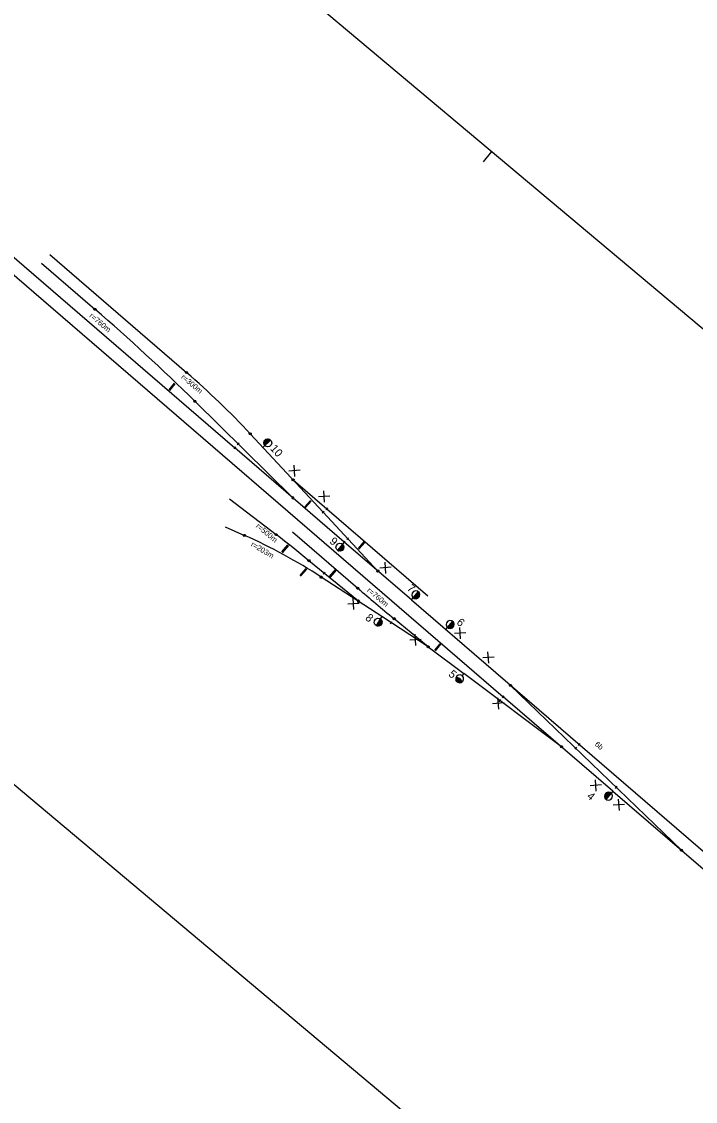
# Model space of a CAD drawing. Extents: x -473608 to -471381, y -1324122 to -1322275.
# Drawn here: x -472467.4 to -472214.7, y -1323575.9 to -1323171.1 of the extents above; entities that cross this region are included whole.
import ezdxf

# ---------------------------------------------------------------- set-up
doc = ezdxf.new("R2010")
doc.units = 0
for name, color, linetype in [('Level 1', 7, 'Continuous'), ('Level 10', 7, 'Continuous'), ('Level 11', 7, 'Continuous'), ('Level 61', 7, 'Continuous')]:
    doc.layers.add(name, color=color, linetype=linetype)

msp = doc.modelspace()

# ---------------------------------------------------------------- linework, layer by layer
at = {"layer": 'Level 1'}
for p, q in [((-472667.69, -1323096.2), (-472286.75, -1323424.15)), ((-472664.42, -1323092.41), (-472387.48, -1323330.83)), ((-472459.93, -1323261.65), (-472439.88, -1323278.91)), ((-472456.85, -1323258.45), (-472405.55, -1323302.62)), ((-472439.88, -1323278.91), (-472439.88, -1323278.91)), ((-472405.55, -1323302.62), (-472405.55, -1323302.62)), ((-472365.7, -1323349.58), (-472402.43, -1323313.4)), ((-472402.43, -1323313.4), (-472402.43, -1323313.4)), ((-472381.63, -1323325.64), (-472354.29, -1323355.02)), ((-472381.63, -1323325.64), (-472381.63, -1323325.64)), ((-472387.16, -1323330.45), (-472387.81, -1323331.21)), ((-472346.4, -1323366.2), (-472387.48, -1323330.83)), ((-472387.48, -1323330.83), (-472387.48, -1323330.83)), ((-472385.83, -1323329.06), (-472386.53, -1323329.77)), ((-472386.18, -1323329.41), (-472386.18, -1323329.41)), ((-472365.61, -1323342.86), (-472365.61, -1323342.86)), ((-472365.61, -1323342.86), (-472315.12, -1323386.32)), ((-472389.38, -1323349.97), (-472371.92, -1323363.41)), ((-472365.7, -1323349.58), (-472365.7, -1323349.58)), ((-472353.92, -1323354.68), (-472354.66, -1323355.36)), ((-472333.8, -1323377.04), (-472354.29, -1323355.02)), ((-472354.29, -1323355.02), (-472354.29, -1323355.02)), ((-472352.69, -1323353.32), (-472353.34, -1323354.08)), ((-472353.02, -1323353.7), (-472353.02, -1323353.7)), ((-472391.07, -1323360.46), (-472383.79, -1323363.68)), ((-472371.92, -1323363.41), (-472371.92, -1323363.41)), ((-472365.84, -1323362.37), (-472341.31, -1323383.48)), ((-472383.79, -1323363.68), (-472383.79, -1323363.68)), ((-472346.74, -1323366.57), (-472346.05, -1323365.84)), ((-472321.21, -1323387.89), (-472346.4, -1323366.2)), ((-472346.4, -1323366.2), (-472346.4, -1323366.2)), ((-472345.49, -1323365.22), (-472344.76, -1323364.54)), ((-472345.49, -1323365.22), (-472344.76, -1323364.54)), ((-472345.12, -1323364.88), (-472345.12, -1323364.88)), ((-472345.12, -1323364.88), (-472345.12, -1323364.88)), ((-472341.1, -1323388.4), (-472359.63, -1323373.18)), ((-472359.63, -1323373.18), (-472359.63, -1323373.18)), ((-472359.63, -1323373.18), (-472359.63, -1323373.18)), ((-472354.75, -1323378.92), (-472355.3, -1323379.76)), ((-472355.03, -1323379.32), (-472355.03, -1323379.32)), ((-472332.28, -1323394.14), (-472355.02, -1323379.34)), ((-472355.02, -1323379.34), (-472355.02, -1323379.34)), ((-472353.62, -1323377.47), (-472354.26, -1323378.24)), ((-472353.94, -1323377.85), (-472353.94, -1323377.85)), ((-472333.8, -1323377.04), (-472333.8, -1323377.04)), ((-472341.31, -1323383.48), (-472341.31, -1323383.48)), ((-472341.1, -1323388.4), (-472341.1, -1323388.4)), ((-472321.21, -1323387.89), (-472146.88, -1323537.97)), ((-472314.89, -1323405.45), (-472332.28, -1323394.14)), ((-472328.05, -1323395.29), (-472327.41, -1323394.52)), ((-472327.73, -1323394.9), (-472327.73, -1323394.9)), ((-472314.89, -1323405.45), (-472327.73, -1323394.9)), ((-472327.73, -1323394.9), (-472327.73, -1323394.9)), ((-472329.09, -1323396.81), (-472328.54, -1323395.97)), ((-472328.82, -1323396.39), (-472328.82, -1323396.39)), ((-472314.89, -1323405.45), (-472314.89, -1323405.45)), ((-472314.89, -1323405.45), (-472301.6, -1323415.42)), ((-472264.97, -1323442.91), (-472301.6, -1323415.42)), ((-472284.03, -1323419.9), (-472284.03, -1323419.9)), ((-472284.03, -1323419.9), (-472219.91, -1323481.7)), ((-472287.08, -1323424.53), (-472286.43, -1323423.78)), ((-472245.67, -1323459.53), (-472286.75, -1323424.15)), ((-472286.75, -1323424.15), (-472286.75, -1323424.15)), ((-472288.26, -1323426.05), (-472287.66, -1323425.26)), ((-472287.96, -1323425.66), (-472287.96, -1323425.66)), ((-472264.97, -1323442.91), (-472264.97, -1323442.91)), ((-472259.85, -1323443.86), (-472259.21, -1323443.1)), ((-472259.53, -1323443.48), (-472259.53, -1323443.48)), ((-472258.56, -1323442.47), (-472257.92, -1323441.7)), ((-472258.24, -1323442.08), (-472258.24, -1323442.08)), ((-472245.67, -1323459.53), (-472195.63, -1323502.6)), ((-472244.7, -1323458.51), (-472244.06, -1323457.74)), ((-472244.38, -1323458.12), (-472244.38, -1323458.12)), ((-472219.91, -1323481.7), (-472219.91, -1323481.7))]:
    msp.add_line(p, q, dxfattribs=at)
for points in [[(-472439.62, -1323278.61), (-472439.49, -1323278.99), (-472439.75, -1323279.29), (-472440.14, -1323279.22), (-472440.27, -1323278.84), (-472440.02, -1323278.53), (-472439.62, -1323278.61)], [(-472405.29, -1323302.32), (-472405.15, -1323302.7), (-472405.41, -1323303), (-472405.81, -1323302.93), (-472405.94, -1323302.55), (-472405.68, -1323302.25), (-472405.29, -1323302.32)], [(-472402.72, -1323313.69), (-472402.82, -1323313.3), (-472402.54, -1323313.02), (-472402.16, -1323313.12), (-472402.05, -1323313.5), (-472402.33, -1323313.79), (-472402.72, -1323313.69)], [(-472381.92, -1323325.91), (-472382.01, -1323325.52), (-472381.72, -1323325.25), (-472381.34, -1323325.37), (-472381.25, -1323325.76), (-472381.54, -1323326.03), (-472381.92, -1323325.91)], [(-472365.34, -1323343.15), (-472365.73, -1323343.24), (-472366, -1323342.95), (-472365.88, -1323342.56), (-472365.49, -1323342.48), (-472365.22, -1323342.77), (-472365.34, -1323343.15)], [(-472365.98, -1323349.87), (-472365.59, -1323349.97), (-472365.32, -1323349.69), (-472365.42, -1323349.3), (-472365.81, -1323349.2), (-472366.09, -1323349.48), (-472365.98, -1323349.87)], [(-472383.62, -1323363.31), (-472383.39, -1323363.64), (-472383.55, -1323364), (-472383.95, -1323364.05), (-472384.18, -1323363.72), (-472384.02, -1323363.36), (-472383.62, -1323363.31)], [(-472371.68, -1323363.09), (-472371.53, -1323363.46), (-472371.77, -1323363.78), (-472372.17, -1323363.73), (-472372.32, -1323363.35), (-472372.07, -1323363.04), (-472371.68, -1323363.09)], [(-472359.88, -1323373.49), (-472360.02, -1323373.12), (-472359.77, -1323372.81), (-472359.38, -1323372.87), (-472359.24, -1323373.25), (-472359.49, -1323373.56), (-472359.88, -1323373.49)], [(-472359.38, -1323372.87), (-472359.24, -1323373.25), (-472359.49, -1323373.55), (-472359.88, -1323373.49), (-472360.02, -1323373.11), (-472359.77, -1323372.81), (-472359.38, -1323372.87)], [(-472355.25, -1323379.66), (-472355.43, -1323379.3), (-472355.22, -1323378.97), (-472354.82, -1323378.99), (-472354.64, -1323379.35), (-472354.85, -1323379.68), (-472355.25, -1323379.66)], [(-472334.11, -1323376.78), (-472333.73, -1323376.65), (-472333.43, -1323376.91), (-472333.5, -1323377.3), (-472333.88, -1323377.44), (-472334.18, -1323377.18), (-472334.11, -1323376.78)], [(-472341.05, -1323383.18), (-472340.92, -1323383.56), (-472341.18, -1323383.86), (-472341.57, -1323383.79), (-472341.7, -1323383.41), (-472341.45, -1323383.11), (-472341.05, -1323383.18)], [(-472341.43, -1323388.18), (-472341.45, -1323388.58), (-472341.12, -1323388.79), (-472340.76, -1323388.61), (-472340.74, -1323388.21), (-472341.07, -1323388), (-472341.43, -1323388.18)], [(-472327.98, -1323395.21), (-472328.12, -1323394.84), (-472327.87, -1323394.53), (-472327.48, -1323394.59), (-472327.34, -1323394.97), (-472327.59, -1323395.28), (-472327.98, -1323395.21)], [(-472315.2, -1323405.19), (-472314.82, -1323405.05), (-472314.52, -1323405.31), (-472314.58, -1323405.7), (-472314.95, -1323405.84), (-472315.26, -1323405.59), (-472315.2, -1323405.19)], [(-472283.77, -1323419.59), (-472283.64, -1323419.97), (-472283.89, -1323420.27), (-472284.29, -1323420.2), (-472284.42, -1323419.83), (-472284.17, -1323419.52), (-472283.77, -1323419.59)], [(-472264.73, -1323442.59), (-472264.57, -1323442.95), (-472264.81, -1323443.27), (-472265.21, -1323443.23), (-472265.36, -1323442.86), (-472265.13, -1323442.54), (-472264.73, -1323442.59)], [(-472219.65, -1323481.4), (-472219.51, -1323481.77), (-472219.77, -1323482.08), (-472220.16, -1323482.01), (-472220.3, -1323481.63), (-472220.04, -1323481.33), (-472219.65, -1323481.4)]]:
    msp.add_lwpolyline(points, dxfattribs=at)
for centre, radius, start, end in [((-472935.74, -1323854.87), 760, 45.43543, 49.27415), ((-472601.28, -1323529.97), 300, 42.9302, 49.2728), ((-472676.88, -1323759.64), 500, 50.6169, 52.4163), ((-472467, -1323550.79), 204.78, 56.8504, 66.023), ((-471845.46, -1322807.52), 760, 229.27439, 230.61225)]:
    msp.add_arc(centre, radius, start, end, dxfattribs=at)
at = {"layer": 'Level 10'}
for p, q in [((-472412.09, -1323309.13), (-472410.03, -1323306.68)), ((-472411.83, -1323309.35), (-472409.77, -1323306.89)), ((-472361.15, -1323353.04), (-472359.09, -1323350.59)), ((-472360.89, -1323353.26), (-472358.83, -1323350.81)), ((-472367.7, -1323367.22), (-472369.98, -1323369.87)), ((-472367.36, -1323367.51), (-472369.64, -1323370.17)), ((-472338.95, -1323365.91), (-472341.23, -1323368.56)), ((-472338.6, -1323366.2), (-472340.89, -1323368.86)), ((-472360.84, -1323376.06), (-472363.12, -1323378.71)), ((-472360.49, -1323376.36), (-472362.78, -1323379.01)), ((-472349.73, -1323376.39), (-472352.01, -1323379.04)), ((-472349.39, -1323376.69), (-472351.67, -1323379.34)), ((-472312.46, -1323406.72), (-472310.4, -1323404.27)), ((-472312.2, -1323406.94), (-472310.14, -1323404.49))]:
    msp.add_line(p, q, dxfattribs=at)
at = {"layer": 'Level 11'}
for p, q in [((-472376.93, -1323330.69), (-472374.04, -1323327.99)), ((-472376.93, -1323330.69), (-472376.93, -1323330.69)), ((-472364.9, -1323341.56), (-472365.22, -1323337.3)), ((-472362.92, -1323339.27), (-472367.19, -1323339.59)), ((-472353.76, -1323351.21), (-472354.08, -1323346.95)), ((-472351.79, -1323348.92), (-472356.05, -1323349.24)), ((-472346.4, -1323366.2), (-472348.94, -1323369.23)), ((-472346.4, -1323366.2), (-472346.4, -1323366.2)), ((-472328.83, -1323375.65), (-472333.1, -1323375.97)), ((-472330.8, -1323377.95), (-472331.12, -1323373.68)), ((-472342.77, -1323391.45), (-472343.09, -1323387.19)), ((-472321.21, -1323387.89), (-472318.67, -1323384.86)), ((-472340.79, -1323389.16), (-472345.06, -1323389.48)), ((-472321.21, -1323387.89), (-472321.21, -1323387.89)), ((-472332.28, -1323394.14), (-472334.48, -1323397.41)), ((-472332.28, -1323394.14), (-472332.28, -1323394.14)), ((-472308.3, -1323399), (-472305.76, -1323395.98)), ((-472308.3, -1323399), (-472308.3, -1323399)), ((-472302.76, -1323402.48), (-472303.08, -1323398.21)), ((-472317.56, -1323402.66), (-472321.83, -1323402.99)), ((-472319.53, -1323404.96), (-472319.85, -1323400.69)), ((-472300.79, -1323400.18), (-472305.05, -1323400.51)), ((-472292.18, -1323411.57), (-472292.5, -1323407.31)), ((-472290.2, -1323409.28), (-472294.47, -1323409.6)), ((-472303.72, -1323416.04), (-472304.3, -1323416.52)), ((-472302.98, -1323415.91), (-472303.72, -1323416.04)), ((-472302.2, -1323416.22), (-472302.98, -1323415.91)), ((-472301.6, -1323415.42), (-472302.2, -1323416.22)), ((-472304.3, -1323416.52), (-472304.6, -1323417.23)), ((-472304.6, -1323417.23), (-472304.51, -1323417.95)), ((-472304.51, -1323417.95), (-472304, -1323418.62)), ((-472304, -1323418.62), (-472304.51, -1323417.97)), ((-472303.95, -1323417.05), (-472304.36, -1323417.6)), ((-472304.36, -1323417.6), (-472304.24, -1323417.94)), ((-472304.24, -1323417.94), (-472303.6, -1323417.09)), ((-472303.31, -1323417.2), (-472304.06, -1323418.2)), ((-472304.06, -1323418.2), (-472304, -1323418.62)), ((-472304, -1323418.62), (-472303.05, -1323417.35)), ((-472304, -1323418.62), (-472303.05, -1323417.35)), ((-472303.58, -1323418.56), (-472304, -1323418.62)), ((-472304, -1323418.62), (-472303.23, -1323418.93)), ((-472302.83, -1323417.56), (-472303.58, -1323418.56)), ((-472303.28, -1323418.66), (-472302.64, -1323417.81)), ((-472302.92, -1323418.68), (-472303.28, -1323418.66)), ((-472303.23, -1323418.93), (-472302.52, -1323418.79)), ((-472302.51, -1323418.14), (-472302.92, -1323418.68)), ((-472302.52, -1323418.79), (-472301.9, -1323418.32)), ((-472301.7, -1323416.89), (-472302.2, -1323416.22)), ((-472301.9, -1323418.32), (-472301.64, -1323417.64)), ((-472301.64, -1323417.64), (-472301.7, -1323416.89)), ((-472286.49, -1323426.51), (-472290.76, -1323426.83)), ((-472288.46, -1323428.8), (-472288.78, -1323424.53)), ((-472251.9, -1323459.53), (-472252.22, -1323455.27)), ((-472249.92, -1323457.24), (-472254.19, -1323457.56)), ((-472245.67, -1323459.53), (-472248.2, -1323462.55)), ((-472245.67, -1323459.53), (-472245.67, -1323459.53)), ((-472241.27, -1323464.54), (-472245.53, -1323464.86)), ((-472243.24, -1323466.83), (-472243.56, -1323462.57))]:
    msp.add_line(p, q, dxfattribs=at)
for points in [[(-472374.32, -1323327.7), (-472373.77, -1323328.28), (-472373.6, -1323329.06), (-472373.82, -1323329.77), (-472374.4, -1323330.31), (-472375.15, -1323330.48), (-472375.89, -1323330.27), (-472376.43, -1323329.68), (-472376.6, -1323328.93), (-472376.38, -1323328.19), (-472375.81, -1323327.66), (-472375.05, -1323327.48), (-472374.32, -1323327.7), (-472374.67, -1323327.69), (-472374.33, -1323328.05), (-472374.55, -1323328.26), (-472375.13, -1323327.64), (-472375.45, -1323327.73), (-472374.77, -1323328.46), (-472374.99, -1323328.67), (-472375.77, -1323327.83), (-472375.99, -1323328.03), (-472375.21, -1323328.87), (-472375.42, -1323329.08), (-472376.21, -1323328.24), (-472376.33, -1323328.55), (-472375.64, -1323329.28), (-472375.86, -1323329.49), (-472376.41, -1323328.9), (-472376.39, -1323329.36), (-472376.08, -1323329.69)], [(-472348.63, -1323369.49), (-472349.24, -1323368.97), (-472349.5, -1323368.22), (-472349.36, -1323367.48), (-472348.86, -1323366.89), (-472348.14, -1323366.62), (-472347.38, -1323366.75), (-472346.77, -1323367.26), (-472346.51, -1323367.99), (-472346.64, -1323368.74), (-472347.15, -1323369.36), (-472347.87, -1323369.61), (-472348.63, -1323369.49), (-472348.28, -1323369.46), (-472348.66, -1323369.13), (-472348.47, -1323368.9), (-472347.82, -1323369.45), (-472347.47, -1323369.35), (-472348.28, -1323368.67), (-472348.08, -1323368.44), (-472347.2, -1323369.18), (-472347.01, -1323368.95), (-472347.89, -1323368.22), (-472347.7, -1323367.99), (-472346.82, -1323368.72), (-472346.74, -1323368.4), (-472347.5, -1323367.76), (-472347.31, -1323367.53), (-472346.66, -1323368.07), (-472346.73, -1323367.62), (-472347.12, -1323367.29)], [(-472318.37, -1323385.12), (-472318.98, -1323384.6), (-472319.74, -1323384.48), (-472320.46, -1323384.73), (-472320.97, -1323385.34), (-472321.1, -1323386.1), (-472320.82, -1323386.85), (-472320.24, -1323387.33), (-472319.47, -1323387.47), (-472318.75, -1323387.21), (-472318.24, -1323386.6), (-472318.11, -1323385.84), (-472318.37, -1323385.12), (-472318.34, -1323385.47), (-472318.72, -1323385.15), (-472318.91, -1323385.38), (-472318.26, -1323385.92), (-472318.3, -1323386.28), (-472319.1, -1323385.61), (-472319.3, -1323385.84), (-472318.42, -1323386.58), (-472318.61, -1323386.81), (-472319.49, -1323386.07), (-472319.68, -1323386.3), (-472318.8, -1323387.03), (-472319.11, -1323387.17), (-472319.88, -1323386.53), (-472320.07, -1323386.76), (-472319.42, -1323387.3), (-472319.92, -1323387.28), (-472320.26, -1323386.99)], [(-472334.15, -1323397.63), (-472334.82, -1323397.19), (-472335.15, -1323396.47), (-472335.09, -1323395.72), (-472334.66, -1323395.08), (-472333.96, -1323394.74), (-472333.19, -1323394.78), (-472332.53, -1323395.23), (-472332.2, -1323395.92), (-472332.25, -1323396.69), (-472332.7, -1323397.35), (-472333.39, -1323397.68), (-472334.15, -1323397.63), (-472333.8, -1323397.57), (-472334.22, -1323397.29), (-472334.05, -1323397.04), (-472333.35, -1323397.51), (-472333.01, -1323397.38), (-472333.88, -1323396.79), (-472333.72, -1323396.54), (-472332.76, -1323397.18), (-472332.6, -1323396.94), (-472333.55, -1323396.29), (-472333.38, -1323396.04), (-472332.43, -1323396.69), (-472332.38, -1323396.35), (-472333.21, -1323395.79), (-472333.04, -1323395.55), (-472332.34, -1323396.02), (-472332.46, -1323395.58), (-472332.88, -1323395.3)], [(-472305.45, -1323396.23), (-472306.07, -1323395.72), (-472306.82, -1323395.59), (-472307.55, -1323395.85), (-472308.06, -1323396.46), (-472308.19, -1323397.22), (-472307.91, -1323397.97), (-472307.33, -1323398.45), (-472306.56, -1323398.58), (-472305.84, -1323398.32), (-472305.32, -1323397.71), (-472305.2, -1323396.96), (-472305.45, -1323396.23), (-472305.42, -1323396.58), (-472305.81, -1323396.26), (-472306, -1323396.49), (-472305.35, -1323397.04), (-472305.39, -1323397.4), (-472306.19, -1323396.72), (-472306.38, -1323396.95), (-472305.5, -1323397.69), (-472305.7, -1323397.92), (-472306.58, -1323397.18), (-472306.77, -1323397.41), (-472305.89, -1323398.15), (-472306.2, -1323398.29), (-472306.96, -1323397.64), (-472307.16, -1323397.87), (-472306.5, -1323398.42), (-472307, -1323398.39), (-472307.35, -1323398.1)], [(-472248.51, -1323462.29), (-472247.9, -1323462.81), (-472247.14, -1323462.94), (-472246.42, -1323462.68), (-472245.9, -1323462.07), (-472245.78, -1323461.31), (-472246.03, -1323460.59), (-472246.65, -1323460.07), (-472247.4, -1323459.95), (-472248.13, -1323460.2), (-472248.64, -1323460.81), (-472248.77, -1323461.57), (-472248.51, -1323462.29), (-472248.54, -1323461.94), (-472248.16, -1323462.26), (-472247.97, -1323462.03), (-472248.62, -1323461.49), (-472248.54, -1323461.16), (-472247.77, -1323461.8), (-472247.58, -1323461.57), (-472248.46, -1323460.83), (-472248.27, -1323460.6), (-472247.39, -1323461.34), (-472247.19, -1323461.11), (-472248.08, -1323460.38), (-472247.77, -1323460.24), (-472247, -1323460.88), (-472246.81, -1323460.65), (-472247.46, -1323460.11), (-472246.96, -1323460.14), (-472246.62, -1323460.42)]]:
    msp.add_lwpolyline(points, dxfattribs=at)
msp.add_arc((-472303.95, -1323418.55), 1.5, 351.3436, 114.8884, dxfattribs=at)
at = {"layer": 'Level 61'}
for p, q in [((-472612.76, -1322949.83), (-471486.68, -1323894.73)), ((-471677.59, -1324122.25), (-472803.67, -1323177.35)), ((-472294.24, -1323223.64), (-472291.02, -1323219.8))]:
    msp.add_line(p, q, dxfattribs=at)

# ---------------------------------------------------------------- texts
at = {"layer": 'Level 10'}
for s, rotation, p in [('r=760m', 320, (-472442.17, -1323281.67)), ('r=300m', 320, (-472407.78, -1323304.63)), ('r=500m', 320, (-472379.71, -1323360.48)), ('r=203m', 329.3813, (-472381.62, -1323367.6)), ('r=760m', 320, (-472338.05, -1323384.56))]:
    msp.add_text(s, height=2, rotation=rotation, dxfattribs=at).set_placement(p)
at = {"layer": 'Level 11'}
for s, height, rotation, p in [('10', 3, 311.5926, (-472374.38, -1323331.24)), ('9', 3, 319.3, (-472352.15, -1323366.3)), ('7', 3, 319.3, (-472323.1, -1323383.91)), ('8', 3, 319.3, (-472338.76, -1323394.99)), ('6', 3, 319.3, (-472304.53, -1323396.68)), ('5', 3, 319.3, (-472307.56, -1323416.09)), ('6b', 2, 319.3, (-472252.62, -1323442.24)), ('4', 3, 319.3, (-472255.66, -1323461.84))]:
    msp.add_text(s, height=height, rotation=rotation, dxfattribs=at).set_placement(p)

doc.saveas('drawing.dxf')
